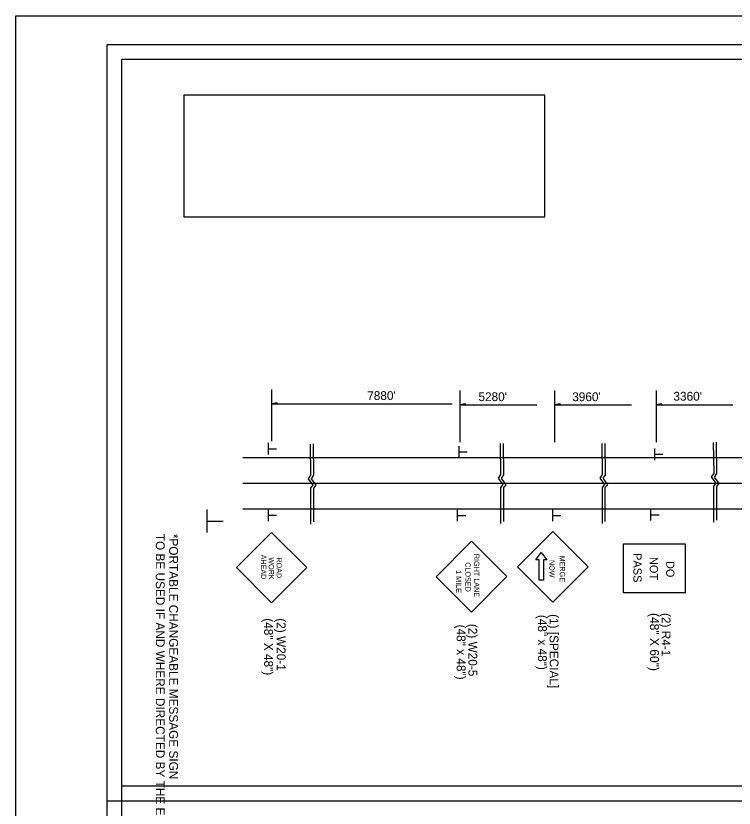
# Model space of a CAD drawing. Extents: x 13528 to 25043, y 7635 to 10612.
# Drawn here: x 15554 to 16041, y 10073 to 10612 of the extents above; entities that cross this region are included whole.
import ezdxf

# ---------------------------------------------------------------- set-up
doc = ezdxf.new("R2010")
doc.units = 0
for name, color, linetype in [('Default', 7, 'Continuous'), ('R_Border Plan-Plan', 7, 'Continuous'), ('R_Border Title', 7, 'Continuous'), ('R_Draft', 7, 'Continuous'), ('R_Revision Date Text', 7, 'Continuous')]:
    doc.layers.add(name, color=color, linetype=linetype)

msp = doc.modelspace()

# ---------------------------------------------------------------- linework, layer by layer
at = {"layer": 'Default'}
for p, q in [((15727.42, 10357.86), (15727.42, 10322.65)), ((15855.34, 10357.19), (15855.34, 10321.98)), ((15919.5, 10357.19), (15919.5, 10321.98)), ((15988.51, 10357.19), (15988.51, 10321.98)), ((15731.17, 10348.63), (15727.42, 10348.07)), ((15731.17, 10348.54), (15728.05, 10348.07)), ((15731.17, 10348.44), (15728.69, 10348.07)), ((15731.17, 10348.35), (15729.31, 10348.07)), ((15731.17, 10348.25), (15729.95, 10348.07)), ((15731.17, 10348.16), (15730.58, 10348.07)), ((15731.17, 10347.5), (15731.17, 10348.63)), ((15727.42, 10348.07), (15850.05, 10348.07)), ((15731.17, 10347.5), (15727.42, 10348.07)), ((15731.17, 10347.6), (15728.05, 10348.07)), ((15731.17, 10347.69), (15728.69, 10348.07)), ((15731.17, 10347.79), (15729.31, 10348.07)), ((15731.17, 10347.89), (15729.95, 10348.07)), ((15731.17, 10347.98), (15730.58, 10348.07)), ((15859.09, 10347.96), (15855.34, 10347.4)), ((15855.34, 10347.4), (15907.53, 10347.4)), ((15859.09, 10346.84), (15855.34, 10347.4)), ((15859.09, 10347.87), (15855.97, 10347.4)), ((15859.09, 10346.93), (15855.97, 10347.4)), ((15859.09, 10347.77), (15856.61, 10347.4)), ((15859.09, 10347.03), (15856.61, 10347.4)), ((15859.09, 10347.68), (15857.24, 10347.4)), ((15859.09, 10347.12), (15857.24, 10347.4)), ((15859.09, 10347.58), (15857.87, 10347.4)), ((15859.09, 10347.22), (15857.87, 10347.4)), ((15859.09, 10347.49), (15858.5, 10347.4)), ((15859.09, 10347.31), (15858.5, 10347.4)), ((15859.09, 10346.84), (15859.09, 10347.96)), ((15923.25, 10347.96), (15919.5, 10347.4)), ((15919.5, 10347.4), (15971.69, 10347.4)), ((15923.25, 10346.84), (15919.5, 10347.4)), ((15923.25, 10347.87), (15920.13, 10347.4)), ((15923.25, 10346.93), (15920.13, 10347.4)), ((15923.25, 10347.77), (15920.77, 10347.4)), ((15923.25, 10347.03), (15920.77, 10347.4)), ((15923.25, 10347.68), (15921.4, 10347.4)), ((15923.25, 10347.12), (15921.4, 10347.4)), ((15923.25, 10347.58), (15922.03, 10347.4)), ((15923.25, 10347.22), (15922.03, 10347.4)), ((15923.25, 10347.49), (15922.66, 10347.4)), ((15923.25, 10347.31), (15922.66, 10347.4)), ((15923.25, 10346.84), (15923.25, 10347.96)), ((15992.26, 10347.96), (15988.51, 10347.4)), ((15988.51, 10347.4), (16040.69, 10347.4)), ((15992.26, 10346.84), (15988.51, 10347.4)), ((15992.26, 10347.87), (15989.13, 10347.4)), ((15992.26, 10346.93), (15989.13, 10347.4)), ((15992.26, 10347.77), (15989.78, 10347.4)), ((15992.26, 10347.03), (15989.78, 10347.4)), ((15992.26, 10347.68), (15990.4, 10347.4)), ((15992.26, 10347.12), (15990.4, 10347.4)), ((15992.26, 10347.58), (15991.04, 10347.4)), ((15992.26, 10347.22), (15991.04, 10347.4)), ((15992.26, 10347.49), (15991.66, 10347.4)), ((15992.26, 10347.31), (15991.66, 10347.4)), ((15992.26, 10346.84), (15992.26, 10347.96)), ((15725.34, 10313.63), (15725.34, 10321.45)), ((15725.46, 10317.52), (15730.8, 10317.52)), ((15854.72, 10311.54), (15854.72, 10319.37)), ((15987.59, 10309.85), (15987.59, 10317.67)), ((15707.9, 10311.48), (15776.68, 10311.48)), ((15776.68, 10311.48), (15810.93, 10311.48)), ((15810.93, 10311.48), (15877.55, 10311.48)), ((15854.84, 10315.44), (15860.18, 10315.44)), ((15877.55, 10311.48), (15946.55, 10311.48)), ((15946.55, 10311.48), (16020.49, 10311.48)), ((15987.71, 10313.74), (15993.05, 10313.74)), ((16020.49, 10311.48), (16082.46, 10311.48)), ((15707.9, 10294.1), (15777.44, 10294.1)), ((15777.44, 10294.1), (15816.37, 10294.1)), ((15816.37, 10294.1), (15877.55, 10294.1)), ((15877.55, 10294.1), (15946.55, 10294.1)), ((15946.55, 10294.1), (16020.95, 10294.1)), ((16020.95, 10294.1), (16082.12, 10294.1)), ((15683.63, 10260.67), (15683.63, 10276.31)), ((15707.9, 10276.71), (15776.73, 10276.71)), ((15725.24, 10268.44), (15725.24, 10276.27)), ((15776.73, 10276.71), (15810.98, 10276.71)), ((15810.98, 10276.71), (15877.55, 10276.71)), ((15853.75, 10268.28), (15853.75, 10276.11)), ((15877.55, 10276.71), (15946.55, 10276.71)), ((15918.35, 10268.23), (15918.35, 10276.05)), ((15946.55, 10276.71), (16021.41, 10276.71)), ((15985.02, 10268.79), (15985.02, 10276.62)), ((16021.41, 10276.71), (16081.79, 10276.71)), ((15683.85, 10268.45), (15694.54, 10268.45)), ((15725.36, 10272.34), (15730.7, 10272.34)), ((15853.87, 10272.17), (15859.21, 10272.17)), ((15918.47, 10272.12), (15923.81, 10272.12)), ((15985.13, 10272.68), (15990.47, 10272.68)), ((15703.57, 10236.8), (15727.45, 10260.71)), ((15751.35, 10236.8), (15727.45, 10260.71)), ((15894.28, 10237.24), (15918.29, 10261.35)), ((15942.37, 10237.33), (15918.29, 10261.35)), ((15839.11, 10230.61), (15863.13, 10254.71)), ((15887.21, 10230.7), (15863.13, 10254.71)), ((15906.78, 10242.1), (15910.53, 10246.96)), ((15910.53, 10246.96), (15914.28, 10242.1)), ((15909.13, 10242.1), (15906.78, 10242.1)), ((15909.13, 10228.3), (15909.13, 10242.1)), ((15911.94, 10242.1), (15911.94, 10228.3)), ((15914.28, 10242.1), (15911.94, 10242.1)), ((15727.45, 10212.9), (15703.57, 10236.8)), ((15727.45, 10212.9), (15751.35, 10236.8)), ((15918.38, 10213.23), (15894.28, 10237.24)), ((15918.38, 10213.23), (15942.37, 10237.33)), ((15863.21, 10206.6), (15839.11, 10230.61)), ((15863.21, 10206.6), (15887.21, 10230.7)), ((15911.94, 10228.3), (15909.13, 10228.3))]:
    msp.add_line(p, q, dxfattribs=at)
for points in [[(16027.28, 10321.84), (16027.6, 10300.81), (16025.98, 10298.4), (16029.14, 10294.07), (16027.47, 10292.07), (16027.47, 10267.61)], [(16029.27, 10322.04), (16029.6, 10300.73), (16027.97, 10298.31), (16031.14, 10293.98), (16029.47, 10291.98), (16029.47, 10269.02)], [(15753.65, 10320.65), (15753.97, 10299.61), (15752.35, 10297.2), (15755.51, 10292.87), (15753.85, 10290.87), (15753.84, 10266.41)], [(15755.65, 10320.84), (15755.97, 10299.53), (15754.35, 10297.11), (15757.51, 10292.78), (15755.84, 10290.78), (15755.84, 10267.82)], [(15882.59, 10320.98), (15882.91, 10299.94), (15881.29, 10297.53), (15884.45, 10293.2), (15882.79, 10291.2), (15882.78, 10266.74)], [(15884.59, 10321.17), (15884.91, 10299.86), (15883.29, 10297.45), (15886.45, 10293.12), (15884.79, 10291.12), (15884.78, 10268.15)], [(15951.6, 10320.98), (15951.92, 10299.94), (15950.29, 10297.53), (15953.46, 10293.2), (15951.79, 10291.2), (15951.79, 10266.74)], [(15953.59, 10321.17), (15953.92, 10299.86), (15952.29, 10297.45), (15955.46, 10293.12), (15953.79, 10291.12), (15953.79, 10268.15)]]:
    msp.add_lwpolyline(points, dxfattribs=at)
msp.add_lwpolyline([(16008.16, 10219.77), (15966.34, 10219.77), (15966.34, 10252.95), (16008.16, 10252.95)], close=True, dxfattribs=at)
at = {"layer": 'R_Border Plan-Plan'}
msp.add_line((15615.87, 10078.42), (17196.77, 10078.42), dxfattribs=at)
at = {"layer": 'R_Border Title'}
msp.add_lwpolyline([(15667.97, 10474.95), (15912.85, 10474.95), (15912.85, 10557.58), (15667.97, 10557.58)], close=True, dxfattribs=at)
at = {"layer": 'R_Draft'}
for p, q in [((15615.87, 10592.07), (17196.77, 10592.07)), ((15615.87, 9564.77), (15615.87, 10592.07))]:
    msp.add_line(p, q, dxfattribs=at)
at = {"layer": 'R_Revision Date Text'}
for points in [[(15553.84, 10611.55), (17220.54, 10611.55), (17220.54, 9544.86), (15553.84, 9544.86)], [(17186.77, 10088.42), (15625.87, 10088.42), (15625.87, 10582.07), (16873.57, 10582.07), (16873.57, 10532.67), (16961.27, 10532.67), (17081.77, 10532.67), (17081.77, 10421.01), (17186.77, 10421.01)], [(15625.87, 10582.07), (16873.57, 10582.07), (16873.57, 10532.67), (16961.27, 10532.67), (17081.77, 10532.67), (17081.77, 10421.01), (17186.77, 10421.01), (17186.77, 9574.77), (15625.87, 9574.77)]]:
    msp.add_lwpolyline(points, close=True, dxfattribs=at)

# ---------------------------------------------------------------- texts
at = {"layer": 'Default'}
for s, p in [("7880'", (15792.36, 10350.6)), ("5280'", (15867.87, 10349.87)), ("3960'", (15931.54, 10349.85)), ("3360'", (16000.24, 10350.18))]:
    msp.add_text(s, height=6, dxfattribs=at).set_placement(p)
for s, height, rotation, p in [('TO BE USED IF AND WHERE DIRECTED BY THE ENGINEER', 6, 270, (15648.87, 10259.74)), ('*PORTABLE CHANGEABLE MESSAGE SIGN', 6, 270, (15657.92, 10259.74)), ('PASS', 5.566, 270, (15973.08, 10246.62)), (' AHEAD', 3.522, 270.0006, (15720.29, 10246.92)), ('WORK', 3.52, 270, (15725.57, 10243.78)), ('ROAD', 3.521, 270.0004, (15730.85, 10243.71)), ('RIGHT LANE', 3.544, 270.1004, (15864.91, 10246.15)), ('NOW', 3.543, 270.1003, (15916, 10241.98)), ('MERGE', 3.544, 270.1004, (15923.09, 10244.91)), ('NOT', 5.566, 270, (15984.21, 10244.03)), ('DO', 5.566, 270, (15995.34, 10241.31)), ('CLOSED', 3.543, 270.1003, (15859.02, 10240.43)), ('1 MILE', 3.567, 270.0006, (15852.61, 10235.12)), ('(48" x 48")', 6, 270, (15908.3, 10204.7)), ('(1) [SPECIAL]', 6, 270, (15916.2, 10205.23)), ('(48" X 60")', 6.1, 270, (15984.35, 10205.96)), ('(2) R4-1', 6, 270, (15992.24, 10205.96)), ('(48" X 48")', 6, 270, (15722.4, 10202.38)), ('(2) W20-1', 6, 270, (15730.96, 10202.38)), ('(48" x 48")', 6, 270, (15853.13, 10198.07)), ('(2) W20-5', 6, 270, (15861.03, 10198.6))]:
    msp.add_text(s, height=height, rotation=rotation, dxfattribs=at).set_placement(p)

doc.saveas('drawing.dxf')
